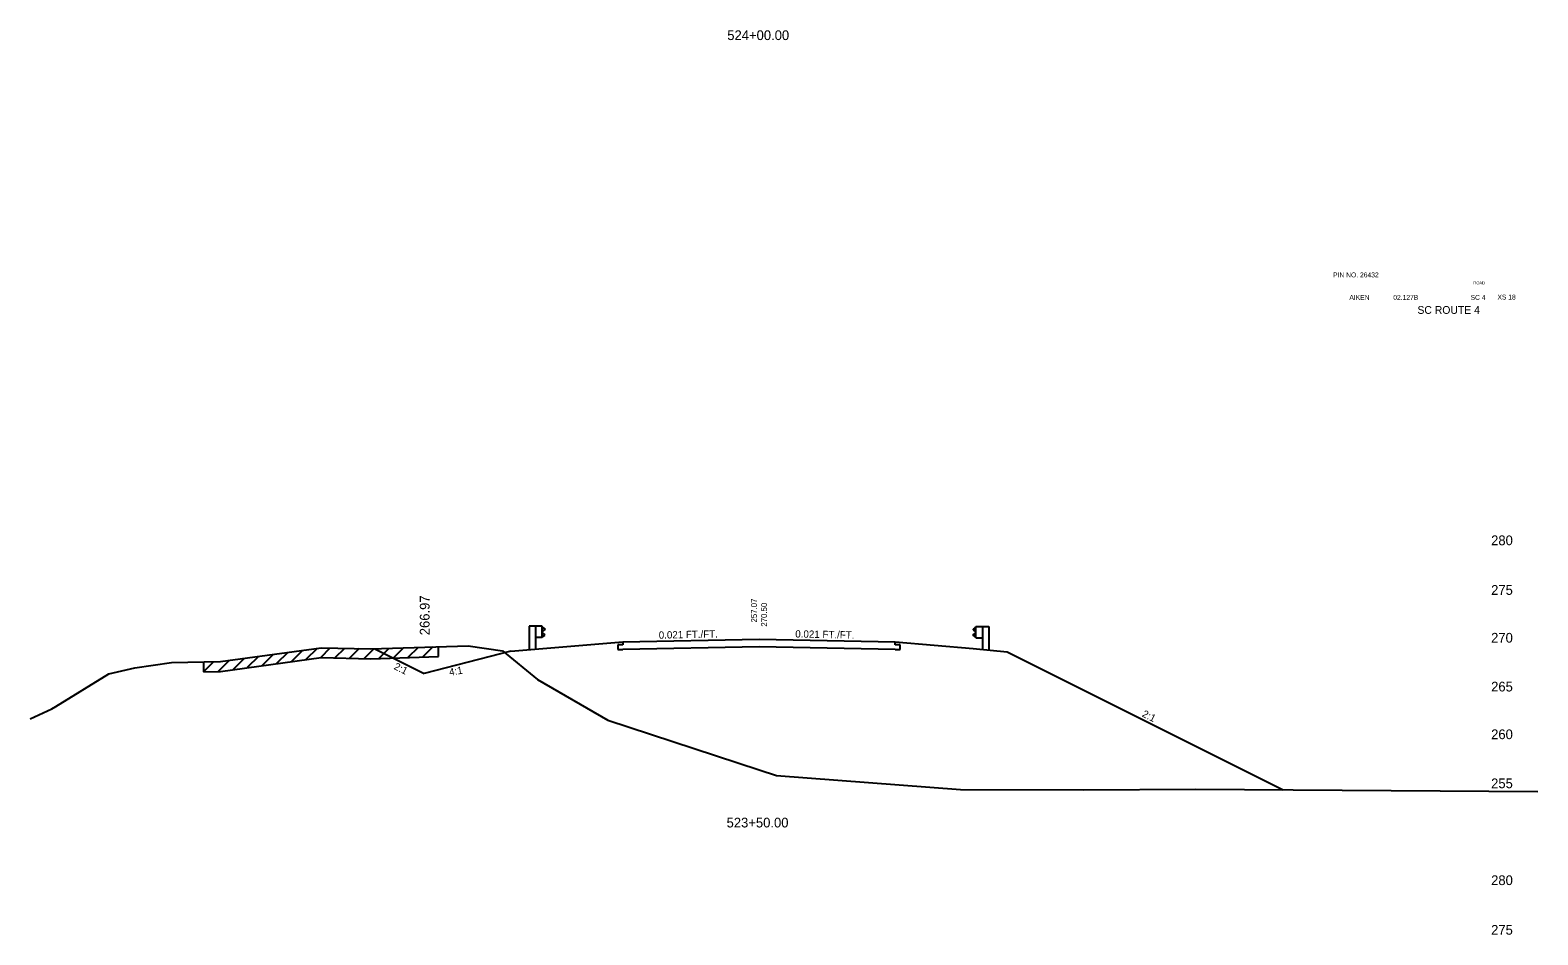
# Model space of a CAD drawing. Extents: x 883 to 1160, y 1002 to 4323.
# Drawn here: x 1005.1 to 1160, y 2990.1 to 3083.1 of the extents above; entities that cross this region are included whole.
import ezdxf

# ---------------------------------------------------------------- set-up
doc = ezdxf.new("R2010")
doc.units = 0
for name, color, linetype in [('Level 1', 7, 'Continuous'), ('Level 10', 7, 'Continuous'), ('Level 11', 7, 'Continuous'), ('Level 12', 7, 'Continuous'), ('Level 24', 7, 'Continuous'), ('Level 3', 7, 'Continuous'), ('Level 32', 7, 'Continuous'), ('Level 33', 7, 'Continuous'), ('Level 59', 7, 'Continuous'), ('Level 6', 7, 'Continuous'), ('Level 60', 7, 'Continuous'), ('Level 61', 7, 'Continuous'), ('Level 7', 7, 'Continuous')]:
    doc.layers.add(name, color=color, linetype=linetype)

msp = doc.modelspace()

# ---------------------------------------------------------------- linework, layer by layer
at = {"layer": 'Level 11'}
for p, q in [((1066, 3019.91), (1065.5, 3019.9)), ((1066, 3020.21), (1066, 3019.91)), ((1094, 3019.91), (1094, 3020.21)), ((1094.5, 3019.9), (1094, 3019.91)), ((1065.5, 3019.9), (1065.5, 3019.42)), ((1065.5, 3019.42), (1066, 3019.43)), ((1094, 3019.43), (1094.5, 3019.42)), ((1094.5, 3019.42), (1094.5, 3019.9))]:
    msp.add_line(p, q, dxfattribs=at)
at = {"layer": 'Level 12'}
for p, q in [((1080, 3019.72), (1066, 3019.43)), ((1094, 3019.43), (1080, 3019.72))]:
    msp.add_line(p, q, dxfattribs=at)
at = {"layer": 'Level 24'}
for p, q in [((1057.05, 3021.82), (1056.39, 3021.82)), ((1056.39, 3021.82), (1056.39, 3019.41)), ((1057.72, 3021.82), (1057.05, 3021.82)), ((1057.05, 3021.82), (1057.05, 3019.46)), ((1057.72, 3020.65), (1057.72, 3021.82)), ((1057.72, 3021.74), (1057.99, 3021.54)), ((1057.99, 3021.49), (1057.72, 3021.29)), ((1057.99, 3021.54), (1057.99, 3021.49)), ((1102.27, 3021.72), (1102, 3021.52)), ((1102, 3021.52), (1102, 3021.47)), ((1102, 3021.47), (1102.27, 3021.27)), ((1102.27, 3020.63), (1102.27, 3021.79)), ((1102.27, 3021.79), (1102.94, 3021.79)), ((1102.94, 3021.79), (1102.94, 3019.45)), ((1102.94, 3021.79), (1103.6, 3021.79)), ((1103.6, 3021.79), (1103.6, 3019.38)), ((1057.72, 3020.65), (1057.05, 3020.65)), ((1057.99, 3020.97), (1057.72, 3021.17)), ((1057.72, 3020.72), (1057.99, 3020.92)), ((1057.99, 3020.92), (1057.99, 3020.97)), ((1102, 3020.95), (1102.27, 3021.15)), ((1102, 3020.9), (1102, 3020.95)), ((1102.27, 3020.7), (1102, 3020.9)), ((1102.27, 3020.63), (1102.94, 3020.63))]:
    msp.add_line(p, q, dxfattribs=at)
at = {"layer": 'Level 59'}
for p, q in [((1066, 3020.21), (1080, 3020.5)), ((1080, 3020.5), (1094, 3020.21))]:
    msp.add_line(p, q, dxfattribs=at)
at = {"layer": 'Level 6'}
for p, q in [((1054.5, 3019.25), (1066, 3020.21)), ((1094, 3020.21), (1102, 3019.54)), ((1102, 3019.54), (1105.5, 3019.19))]:
    msp.add_line(p, q, dxfattribs=at)
at = {"layer": 'Level 60'}
for p, q in [((1024.67, 3018.19), (1035.03, 3019.6)), ((1035.03, 3019.6), (1040.13, 3019.49)), ((1040.13, 3019.49), (1050.13, 3019.82)), ((1050.13, 3019.82), (1053.66, 3019.31)), ((1053.66, 3019.31), (1057.23, 3016.35)), ((1007.77, 3013.59), (1013.22, 3016.95)), ((1013.22, 3016.95), (1015.89, 3017.56)), ((1015.89, 3017.56), (1019.65, 3018.09)), ((1019.65, 3018.09), (1024.67, 3018.19)), ((1057.23, 3016.35), (1064.47, 3012.18)), ((1005.13, 3012.3), (1007.35, 3013.34)), ((1007.35, 3013.34), (1007.77, 3013.59)), ((1064.47, 3012.18), (1080, 3007.07)), ((1080, 3007.07), (1081.78, 3006.48)), ((1081.78, 3006.48), (1100.68, 3005.05)), ((1100.68, 3005.05), (1113.37, 3005)), ((1113.37, 3005), (1124.84, 3005.09)), ((1124.84, 3005.09), (1160, 3004.83))]:
    msp.add_line(p, q, dxfattribs=at)
at = {"layer": 'Level 61'}
for p, q in [((1024.67, 3017.19), (1035.03, 3018.6)), ((1027.1, 3018.52), (1025.94, 3017.36)), ((1028.6, 3018.72), (1027.44, 3017.57)), ((1030.1, 3018.93), (1028.94, 3017.77)), ((1031.6, 3019.13), (1030.44, 3017.98)), ((1033.1, 3019.34), (1031.94, 3018.18)), ((1034.6, 3019.55), (1033.44, 3018.39)), ((1035.93, 3019.58), (1034.94, 3018.59)), ((1035.03, 3018.6), (1040.13, 3018.49)), ((1037.42, 3019.55), (1036.44, 3018.57)), ((1038.92, 3019.52), (1037.94, 3018.54)), ((1040.44, 3019.5), (1039.44, 3018.51)), ((1040.13, 3018.49), (1047.07, 3018.72)), ((1041.98, 3019.55), (1040.94, 3018.52)), ((1043.48, 3019.6), (1042.44, 3018.57)), ((1044.98, 3019.65), (1043.94, 3018.62)), ((1046.48, 3019.7), (1045.44, 3018.66)), ((1047.07, 3018.72), (1047.07, 3019.72)), ((1023.96, 3018.17), (1022.94, 3017.15)), ((1022.94, 3018.15), (1022.94, 3017.15)), ((1022.94, 3017.15), (1024.67, 3017.19)), ((1025.57, 3018.31), (1024.44, 3017.18))]:
    msp.add_line(p, q, dxfattribs=at)
at = {"layer": 'Level 7'}
for p, q in [((1040.55, 3019.51), (1045.62, 3016.97)), ((1054.5, 3019.25), (1045.62, 3016.97)), ((1105.5, 3019.19), (1133.84, 3005.02))]:
    msp.add_line(p, q, dxfattribs=at)

# ---------------------------------------------------------------- texts
at = {"layer": 'Level 1'}
for s, height, p in [('524+00.00', 1, (1076.74, 3082.05)), ('PIN NO. 26432', 0.5, (1138.97, 3057.67)), ('AIKEN', 0.5, (1140.64, 3055.36)), ('02.127B', 0.5, (1145.15, 3055.36)), ('SC 4', 0.5, (1153.09, 3055.36)), ('XS 18', 0.5, (1155.85, 3055.39)), ('SC ROUTE 4', 0.8, (1147.63, 3053.92)), ('523+50.00', 1, (1076.67, 3001.15))]:
    msp.add_text(s, height=height, dxfattribs=at).set_placement(p)
at = {"layer": 'Level 10'}
msp.add_text('257.07', height=0.6, rotation=90, dxfattribs=at).set_placement((1079.79, 3022.21))
at = {"layer": 'Level 3'}
for s, height, p in [('ROAD', 0.3, (1153.38, 3056.95)), (' 280', 1, (1154.83, 3030.15)), (' 275', 1, (1154.83, 3025.05)), (' 270', 1, (1154.83, 3020.14)), (' 265', 1, (1154.83, 3015.12)), (' 260', 1, (1154.83, 3010.22)), (' 255', 1, (1154.83, 3005.18)), (' 280', 1, (1154.83, 2995.23)), (' 275', 1, (1154.83, 2990.13))]:
    msp.add_text(s, height=height, dxfattribs=at).set_placement(p)
at = {"layer": 'Level 32'}
for s, rotation, p in [('0.021 FT./FT.', 1.1916, (1069.71, 3020.54)), ('0.021 FT./FT.', 358.8084, (1083.72, 3020.67)), ('2:1', 333.435, (1042.43, 3017.45)), ('4:1', 9.4623, (1048.23, 3016.73)), ('2:1', 333.435, (1119.28, 3012.58))]:
    msp.add_text(s, height=0.75, rotation=rotation, dxfattribs=at).set_placement(p)
at = {"layer": 'Level 33'}
msp.add_text('266.97', height=1, rotation=90, dxfattribs=at).set_placement((1046.16, 3020.9))
at = {"layer": 'Level 59'}
msp.add_text(' 270.50', height=0.6, rotation=90, dxfattribs=at).set_placement((1080.82, 3021.56))

doc.saveas('drawing.dxf')
